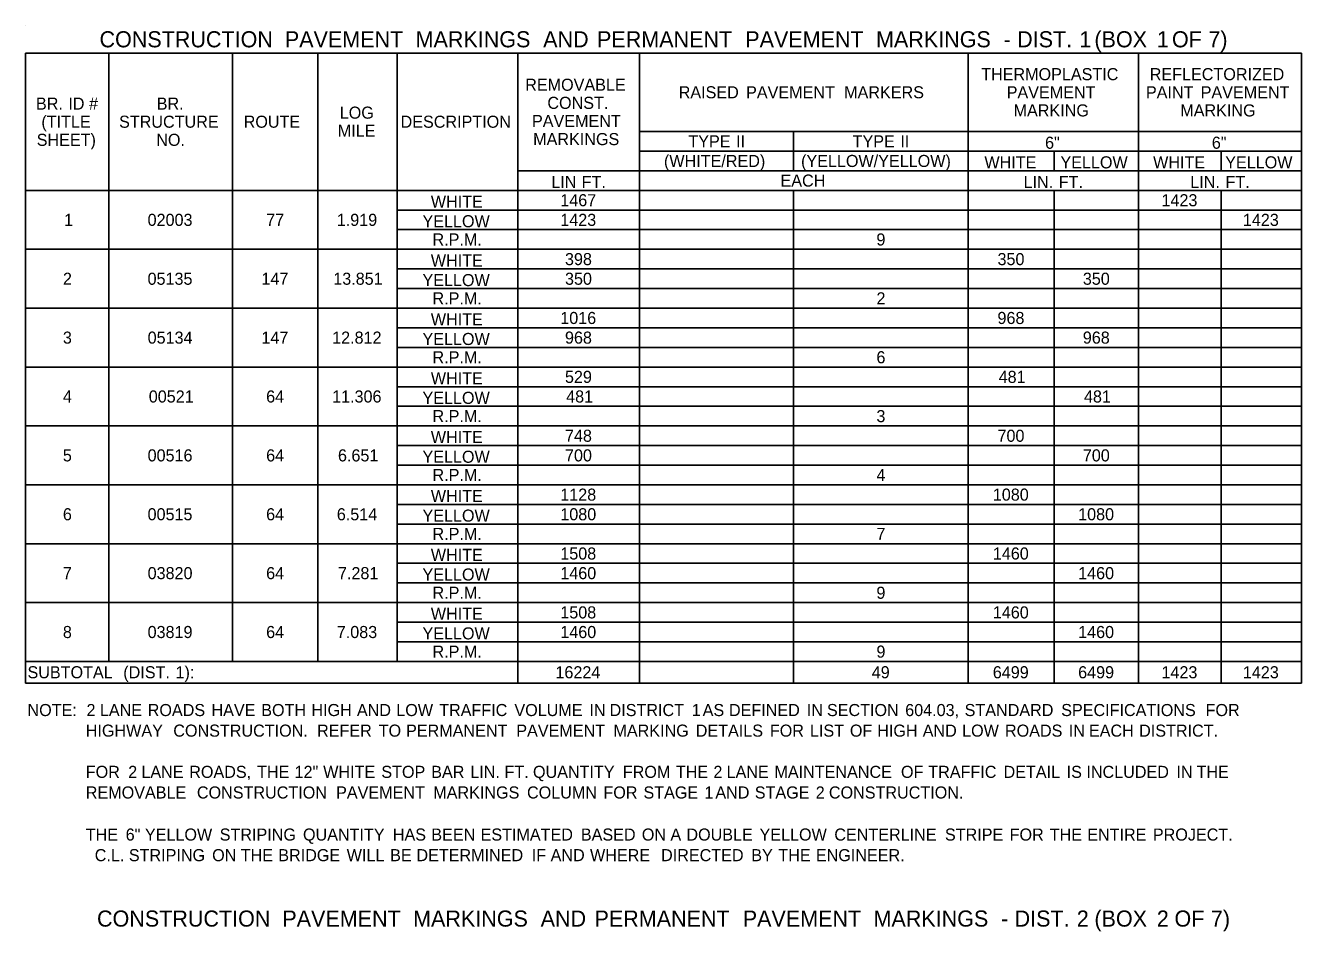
# Model space of a CAD drawing. Extents: x 544255 to 1930787, y -1947044 to 596640.
# Drawn here: x 544255 to 544890, y -1946529 to -1946079 of the extents above; entities that cross this region are included whole.
import ezdxf

# ---------------------------------------------------------------- set-up
doc = ezdxf.new("R2010")
doc.units = 0
doc.layers.add('Default', color=7, linetype='Continuous')

msp = doc.modelspace()

# ---------------------------------------------------------------- linework, layer by layer
at = {"layer": 'Default'}
for p, q in [((544255.45, -1946078.97), (544255.45, -1946078.97)), ((544255.45, -1946092.62), (544889.69, -1946092.62)), ((544255.45, -1946092.62), (544560.63, -1946092.62)), ((544255.45, -1946405.59), (544255.45, -1946092.62)), ((544296.89, -1946394.87), (544296.89, -1946092.62)), ((544358.31, -1946394.87), (544358.31, -1946092.62)), ((544400.73, -1946394.87), (544400.73, -1946092.62)), ((544440.21, -1946394.87), (544440.21, -1946092.62)), ((544500.18, -1946405.59), (544500.18, -1946092.62)), ((544560.63, -1946405.59), (544560.63, -1946092.62)), ((544723.94, -1946405.59), (544723.94, -1946092.62)), ((544808.76, -1946160.87), (544808.76, -1946092.62)), ((544808.76, -1946405.59), (544808.76, -1946092.62)), ((544889.69, -1946405.59), (544889.69, -1946092.62)), ((544560.63, -1946131.62), (544889.69, -1946131.62)), ((544637.16, -1946151.12), (544637.16, -1946131.62)), ((544560.63, -1946141.37), (544889.69, -1946141.37)), ((544766.84, -1946151.12), (544766.84, -1946141.37)), ((544849.71, -1946151.12), (544849.71, -1946141.37)), ((544500.18, -1946151.12), (544889.69, -1946151.12)), ((544500.18, -1946160.87), (544500.18, -1946151.12)), ((544255.45, -1946160.87), (544440.21, -1946160.87)), ((544255.45, -1946160.87), (544400.73, -1946160.87)), ((544400.73, -1946160.87), (544889.69, -1946160.87)), ((544637.16, -1946405.59), (544637.16, -1946160.87)), ((544723.94, -1946160.87), (544808.76, -1946160.87)), ((544766.84, -1946405.59), (544766.84, -1946160.87)), ((544808.76, -1946160.87), (544889.69, -1946160.87)), ((544849.71, -1946405.59), (544849.71, -1946160.87)), ((544440.21, -1946170.62), (544889.69, -1946170.62)), ((544440.21, -1946180.37), (544889.69, -1946180.37)), ((544255.45, -1946190.12), (544889.69, -1946190.12)), ((544440.21, -1946199.87), (544889.69, -1946199.87)), ((544440.21, -1946209.62), (544889.69, -1946209.62)), ((544255.45, -1946219.37), (544889.69, -1946219.37)), ((544440.21, -1946229.12), (544889.69, -1946229.12)), ((544440.21, -1946238.87), (544889.69, -1946238.87)), ((544255.45, -1946248.62), (544889.69, -1946248.62)), ((544440.21, -1946258.37), (544889.69, -1946258.37)), ((544440.21, -1946268.12), (544889.69, -1946268.12)), ((544255.45, -1946277.87), (544889.69, -1946277.87)), ((544440.21, -1946287.62), (544889.69, -1946287.62)), ((544440.21, -1946297.37), (544889.69, -1946297.37)), ((544255.45, -1946307.12), (544889.69, -1946307.12)), ((544440.21, -1946316.87), (544889.69, -1946316.87)), ((544440.21, -1946326.62), (544889.69, -1946326.62)), ((544255.45, -1946336.37), (544889.69, -1946336.37)), ((544440.21, -1946346.12), (544889.69, -1946346.12)), ((544440.21, -1946355.87), (544889.69, -1946355.87)), ((544255.45, -1946365.62), (544889.69, -1946365.62)), ((544440.21, -1946375.37), (544889.69, -1946375.37)), ((544440.21, -1946385.12), (544889.69, -1946385.12)), ((544255.45, -1946394.87), (544889.69, -1946394.87)), ((544500.18, -1946405.59), (544500.18, -1946394.87)), ((544255.45, -1946405.59), (544889.69, -1946405.59))]:
    msp.add_line(p, q, dxfattribs=at)

# ---------------------------------------------------------------- texts
for s, height, p in [(' (BOX', 8, (544783.79, -1946089.79)), (' 7)', 8, (544840.45, -1946089.79)), ('CONSTRUCTION', 8, (544292.24, -1946089.79)), (' PAVEMENT', 8, (544381.39, -1946089.79)), (' MARKINGS', 8, (544446.38, -1946089.79)), (' AND', 8, (544509.79, -1946089.79)), (' PERMANENT', 8, (544536.56, -1946089.79)), (' PAVEMENT', 8, (544610.24, -1946089.79)), (' MARKINGS', 8, (544675.23, -1946089.79)), (' -', 8, (544738.64, -1946089.79)), (' DIST.', 8, (544745.38, -1946089.79)), (' 1', 8, (544776.29, -1946089.79)), (' 1', 8, (544814.83, -1946089.79)), (' OF', 8, (544822.34, -1946089.79)), ('THERMOPLASTIC', 6, (544730.47, -1946106.12)), ('REFLECTORIZED', 6, (544814.27, -1946106.12)), ('REMOVABLE', 6, (544503.83, -1946111.37)), ('RAISED', 6, (544580.13, -1946115.12)), (' PAVEMENT', 6, (544611.39, -1946115.12)), (' MARKERS', 6, (544660.13, -1946115.12)), ('PAVEMENT', 6, (544743.15, -1946115.12)), ('PAINT', 6, (544812.37, -1946115.12)), (' PAVEMENT', 6, (544837.35, -1946115.12)), ('BR.', 6, (544260.65, -1946120.74)), (' ID', 6, (544274.51, -1946120.74)), (' #', 6, (544284.8, -1946120.74)), ('BR.', 6, (544320.67, -1946120.74)), ('LOG', 6, (544411.64, -1946125.24)), ('CONST.', 6, (544514.85, -1946120.37)), ('MARKING', 6, (544746.58, -1946124.12)), ('MARKING', 6, (544829.45, -1946124.12)), ('(TITLE', 6, (544263.34, -1946129.74)), ('STRUCTURE', 6, (544301.96, -1946129.74)), ('ROUTE', 6, (544363.89, -1946129.74)), ('DESCRIPTION', 6, (544441.88, -1946129.74)), ('PAVEMENT', 6, (544507.2, -1946129.37)), ('MILE', 6, (544410.67, -1946134.24)), ('MARKINGS', 6, (544507.79, -1946138.37)), ('SHEET)', 6, (544261.02, -1946138.74)), ('NO.', 6, (544320.44, -1946138.74)), ('TYPE', 6, (544584.93, -1946139.49)), (' II', 6, (544606.42, -1946139.49)), ('TYPE', 6, (544666.59, -1946139.49)), (' II', 6, (544688.07, -1946139.49)), ('6"', 6, (544762.24, -1946140.17)), ('6"', 6, (544845.12, -1946140.17)), ('(WHITE/RED)', 6, (544572.8, -1946149.24)), ('(YELLOW/YELLOW)', 6, (544640.95, -1946149.24)), ('WHITE', 6, (544732.09, -1946149.92)), ('YELLOW', 6, (544769.88, -1946149.92)), ('WHITE', 6, (544815.94, -1946149.92)), ('YELLOW', 6, (544851.78, -1946149.92)), ('LIN', 6, (544516.82, -1946159.67)), (' FT.', 6, (544529.66, -1946159.67)), ('EACH', 6, (544630.73, -1946158.99)), ('LIN.', 6, (544751.56, -1946159.67)), (' FT.', 6, (544766.82, -1946159.67)), ('LIN.', 6, (544834.44, -1946159.67)), (' FT.', 6, (544849.69, -1946159.67)), ('WHITE', 6, (544456.92, -1946169.42)), ('1467', 6, (544521.27, -1946168.74)), ('1423', 6, (544820.11, -1946168.74)), ('1', 6, (544274.61, -1946178.49)), ('02003', 6, (544316.14, -1946178.49)), ('77', 6, (544375.05, -1946178.49)), ('1.919', 6, (544410.17, -1946178.49)), ('YELLOW', 6, (544452.77, -1946179.17)), ('1423', 6, (544521.27, -1946178.49)), ('1423', 6, (544860.57, -1946178.49)), ('R.P.M.', 6, (544457.75, -1946188.24)), ('9', 6, (544678.41, -1946188.24)), ('WHITE', 6, (544456.92, -1946198.67)), ('398', 6, (544523.6, -1946197.99)), ('350', 6, (544738.6, -1946197.99)), ('2', 6, (544274.06, -1946207.74)), ('05135', 6, (544316.12, -1946207.74)), ('147', 6, (544372.72, -1946207.74)), ('13.851', 6, (544408.43, -1946207.74)), ('350', 6, (544523.61, -1946207.74)), ('350', 6, (544781.01, -1946207.74)), ('YELLOW', 6, (544452.77, -1946208.42)), ('R.P.M.', 6, (544457.75, -1946217.49)), ('2', 6, (544678.44, -1946217.49)), ('1016', 6, (544521.27, -1946227.24)), ('968', 6, (544738.58, -1946227.24)), ('WHITE', 6, (544456.92, -1946227.92)), ('3', 6, (544274.03, -1946236.99)), ('05134', 6, (544316.16, -1946236.99)), ('147', 6, (544372.72, -1946236.99)), ('12.812', 6, (544407.88, -1946236.99)), ('YELLOW', 6, (544452.77, -1946237.67)), ('968', 6, (544523.6, -1946236.99)), ('968', 6, (544781, -1946236.99)), ('R.P.M.', 6, (544457.75, -1946246.74)), ('6', 6, (544678.41, -1946246.74)), ('WHITE', 6, (544456.92, -1946257.17)), ('529', 6, (544523.6, -1946256.49)), ('481', 6, (544739.17, -1946256.49)), ('4', 6, (544274.04, -1946266.24)), ('00521', 6, (544316.72, -1946266.24)), ('64', 6, (544375.06, -1946266.24)), ('11.306', 6, (544407.85, -1946266.24)), ('YELLOW', 6, (544452.77, -1946266.92)), ('481', 6, (544524.18, -1946266.24)), ('481', 6, (544781.58, -1946266.24)), ('R.P.M.', 6, (544457.75, -1946275.99)), ('3', 6, (544678.41, -1946275.99)), ('WHITE', 6, (544456.92, -1946286.42)), ('748', 6, (544523.6, -1946285.74)), ('700', 6, (544738.6, -1946285.74)), ('5', 6, (544274.01, -1946295.49)), ('00516', 6, (544316.14, -1946295.49)), ('64', 6, (544375.06, -1946295.49)), ('6.651', 6, (544410.76, -1946295.49)), ('YELLOW', 6, (544452.77, -1946296.17)), ('700', 6, (544523.61, -1946295.49)), ('700', 6, (544781.01, -1946295.49)), ('R.P.M.', 6, (544457.75, -1946305.24)), ('4', 6, (544678.43, -1946305.24)), ('WHITE', 6, (544456.92, -1946315.67)), ('1128', 6, (544521.27, -1946314.99)), ('1080', 6, (544736.27, -1946314.99)), ('6', 6, (544274.03, -1946324.74)), ('00515', 6, (544316.12, -1946324.74)), ('64', 6, (544375.06, -1946324.74)), ('6.514', 6, (544410.19, -1946324.74)), ('YELLOW', 6, (544452.77, -1946325.42)), ('1080', 6, (544521.28, -1946324.74)), ('1080', 6, (544778.68, -1946324.74)), ('R.P.M.', 6, (544457.75, -1946334.49)), ('7', 6, (544678.41, -1946334.49)), ('WHITE', 6, (544456.92, -1946344.92)), ('1508', 6, (544521.27, -1946344.24)), ('1460', 6, (544736.27, -1946344.24)), ('7', 6, (544274.03, -1946353.99)), ('03820', 6, (544316.15, -1946353.99)), ('64', 6, (544375.06, -1946353.99)), ('7.281', 6, (544410.76, -1946353.99)), ('1460', 6, (544521.28, -1946353.99)), ('1460', 6, (544778.68, -1946353.99)), ('YELLOW', 6, (544452.77, -1946354.67)), ('R.P.M.', 6, (544457.75, -1946363.74)), ('9', 6, (544678.41, -1946363.74)), ('WHITE', 6, (544456.92, -1946374.17)), ('1508', 6, (544521.27, -1946373.49)), ('1460', 6, (544736.27, -1946373.49)), ('8', 6, (544274.03, -1946383.24)), ('03819', 6, (544316.14, -1946383.24)), ('64', 6, (544375.06, -1946383.24)), ('7.083', 6, (544410.18, -1946383.24)), ('YELLOW', 6, (544452.77, -1946383.92)), ('1460', 6, (544521.28, -1946383.24)), ('1460', 6, (544778.68, -1946383.24)), ('R.P.M.', 6, (544457.75, -1946392.99)), ('9', 6, (544678.41, -1946392.99)), ('SUBTOTAL', 6, (544256.43, -1946403.23)), (' (DIST.', 6, (544301.82, -1946403.23)), (' 1):', 6, (544327.79, -1946403.23)), ('16224', 6, (544518.85, -1946403.23)), ('49', 6, (544676.09, -1946403.23)), ('6499', 6, (544736.26, -1946403.23)), ('6499', 6, (544778.68, -1946403.23)), ('1423', 6, (544820.1, -1946403.23)), ('1423', 6, (544860.56, -1946403.23)), ('NOTE:', 6, (544256.43, -1946422)), ('  2', 6, (544281.31, -1946422)), (' LANE', 6, (544290.19, -1946422)), (' ROADS', 6, (544313.97, -1946422)), (' HAVE', 6, (544345.67, -1946422)), (' BOTH', 6, (544370.39, -1946422)), (' HIGH', 6, (544395.33, -1946422)), (' AND', 6, (544417.94, -1946422)), (' LOW', 6, (544437.52, -1946422)), (' TRAFFIC', 6, (544458.84, -1946422)), (' VOLUME', 6, (544496.24, -1946422)), (' IN', 6, (544533.52, -1946422)), (' DISTRICT', 6, (544543.54, -1946422)), (' 1', 6, (544584.36, -1946422)), (' AS', 6, (544589.81, -1946422)), (' DEFINED', 6, (544602.88, -1946422)), (' IN', 6, (544641.56, -1946422)), (' SECTION', 6, (544651.59, -1946422)), (' 604.03,', 6, (544690.49, -1946422)), (' STANDARD', 6, (544720.03, -1946422)), (' SPECIFICATIONS', 6, (544768.03, -1946422)), (' FOR', 6, (544839.8, -1946422)), ('             HIGHWAY', 6, (544256.43, -1946432.23)), (' CONSTRUCTION.', 6, (544326.68, -1946432.23)), (' REFER', 6, (544398.14, -1946432.23)), (' TO', 6, (544428.77, -1946432.23)), (' PERMANENT', 6, (544442.37, -1946432.23)), (' PAVEMENT', 6, (544497.17, -1946432.23)), (' MARKING', 6, (544545.45, -1946432.23)), (' DETAILS', 6, (544586.38, -1946432.23)), (' FOR', 6, (544623.21, -1946432.23)), (' LIST', 6, (544643.13, -1946432.23)), (' OF', 6, (544662.99, -1946432.23)), (' HIGH', 6, (544676.57, -1946432.23)), (' AND', 6, (544699.18, -1946432.23)), (' LOW', 6, (544718.77, -1946432.23)), (' ROADS', 6, (544740.09, -1946432.23)), (' IN', 6, (544771.8, -1946432.23)), (' EACH', 6, (544781.82, -1946432.23)), (' DISTRICT.', 6, (544806.77, -1946432.23)), ('             FOR', 6, (544256.43, -1946452.71)), (' 2', 6, (544304.27, -1946452.71)), (' LANE', 6, (544310.82, -1946452.71)), (' ROADS,', 6, (544334.6, -1946452.71)), (' THE', 6, (544368.32, -1946452.71)), (' 12"', 6, (544386.97, -1946452.71)), (' WHITE', 6, (544401.2, -1946452.71)), (' STOP', 6, (544430.09, -1946452.71)), (' BAR', 6, (544454.88, -1946452.71)), (' LIN.', 6, (544474.34, -1946452.71)), (' FT.', 6, (544491.31, -1946452.71)), (' QUANTITY', 6, (544505.47, -1946452.71)), (' FROM', 6, (544550.13, -1946452.71)), (' THE', 6, (544576.5, -1946452.71)), (' 2', 6, (544595.15, -1946452.71)), (' LANE', 6, (544601.7, -1946452.71)), (' MAINTENANCE', 6, (544625.48, -1946452.71)), (' OF', 6, (544688.38, -1946452.71)), (' TRAFFIC', 6, (544701.97, -1946452.71)), (' DETAIL', 6, (544739.36, -1946452.71)), (' IS', 6, (544770.74, -1946452.71)), (' INCLUDED', 6, (544780.55, -1946452.71)), (' IN', 6, (544825.28, -1946452.71)), (' THE', 6, (544835.31, -1946452.71)), ('             REMOVABLE', 6, (544256.43, -1946462.95)), (' CONSTRUCTION', 6, (544338.42, -1946462.95)), (' PAVEMENT', 6, (544407.6, -1946462.95)), (' MARKINGS', 6, (544455.89, -1946462.95)), (' COLUMN', 6, (544502.5, -1946462.95)), (' FOR', 6, (544540.47, -1946462.95)), (' STAGE', 6, (544560.38, -1946462.95)), (' 1', 6, (544590.68, -1946462.95)), (' AND', 6, (544596.13, -1946462.95)), (' STAGE', 6, (544615.71, -1946462.95)), (' 2', 6, (544646.01, -1946462.95)), (' CONSTRUCTION.', 6, (544652.56, -1946462.95)), ('             THE', 6, (544256.43, -1946483.85)), (' 6"', 6, (544303.01, -1946483.85)), (' YELLOW', 6, (544312.58, -1946483.85)), (' STRIPING', 6, (544349.75, -1946483.85)), (' QUANTITY', 6, (544391.15, -1946483.85)), (' HAS', 6, (544435.8, -1946483.85)), (' BEEN', 6, (544454.93, -1946483.85)), (' ESTIMATED', 6, (544479.41, -1946483.85)), (' BASED', 6, (544529.27, -1946483.85)), (' ON', 6, (544559.57, -1946483.85)), (' A', 6, (544573.79, -1946483.85)), (' DOUBLE', 6, (544581.73, -1946483.85)), (' YELLOW', 6, (544618.08, -1946483.85)), (' CENTERLINE', 6, (544655.25, -1946483.85)), (' STRIPE', 6, (544710.24, -1946483.85)), (' FOR', 6, (544742.4, -1946483.85)), (' THE', 6, (544762.32, -1946483.85)), (' ENTIRE', 6, (544780.97, -1946483.85)), (' PROJECT.', 6, (544813.59, -1946483.85)), (' C.L.', 6, (544287.63, -1946494.09)), (' STRIPING', 6, (544304.59, -1946494.09)), (' ON', 6, (544345.99, -1946494.09)), (' THE', 6, (544360.21, -1946494.09)), (' BRIDGE', 6, (544378.86, -1946494.09)), (' WILL', 6, (544412.88, -1946494.09)), (' BE', 6, (544434.47, -1946494.09)), (' DETERMINED', 6, (544447.54, -1946494.09)), (' IF', 6, (544504.85, -1946494.09)), (' AND', 6, (544514.24, -1946494.09)), (' WHERE', 6, (544533.82, -1946494.09)), ('  DIRECTED', 6, (544566.91, -1946494.09)), (' BY', 6, (544613.97, -1946494.09)), (' THE', 6, (544627.42, -1946494.09)), (' ENGINEER.', 6, (544646.07, -1946494.09)), ('CONSTRUCTION', 8, (544290.99, -1946526.59)), (' PAVEMENT', 8, (544380.14, -1946526.59)), (' MARKINGS', 8, (544445.13, -1946526.59)), (' AND', 8, (544508.54, -1946526.59)), (' PERMANENT', 8, (544535.31, -1946526.59)), (' PAVEMENT', 8, (544608.99, -1946526.59)), (' MARKINGS', 8, (544673.98, -1946526.59)), (' DIST.', 8, (544744.13, -1946526.59)), (' 2', 8, (544775.04, -1946526.59)), (' (BOX', 8, (544783.79, -1946526.59)), (' 2', 8, (544814.83, -1946526.59)), (' OF', 8, (544823.59, -1946526.59)), (' 7)', 8, (544841.7, -1946526.59)), (' -', 8, (544737.39, -1946526.59))]:
    msp.add_text(s, height=height, dxfattribs=at).set_placement(p)

doc.saveas('drawing.dxf')
